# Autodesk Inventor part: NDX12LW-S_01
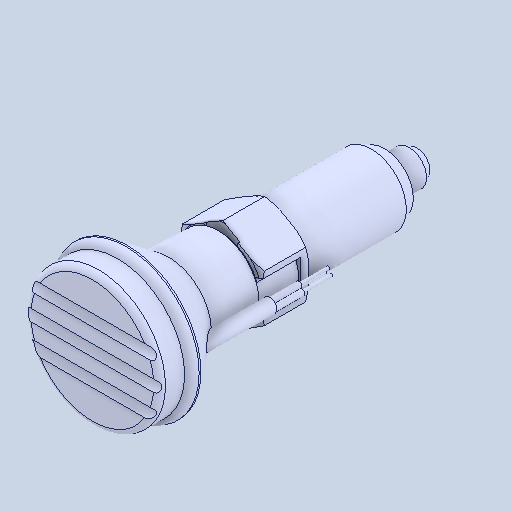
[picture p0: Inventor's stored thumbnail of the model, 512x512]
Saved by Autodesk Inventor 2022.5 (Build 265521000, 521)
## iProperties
Created: 2024-05
Part Number: NDX12LW-S_01
Material: 一般
Document SubType Name: Modeling
Designer: ImaoCorp
Density: 1 g/cm^3
Appearance: 既定
Author: ImaoCorp
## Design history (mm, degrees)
feature "NDX12LW-S_01"
node "ソリッド1"
